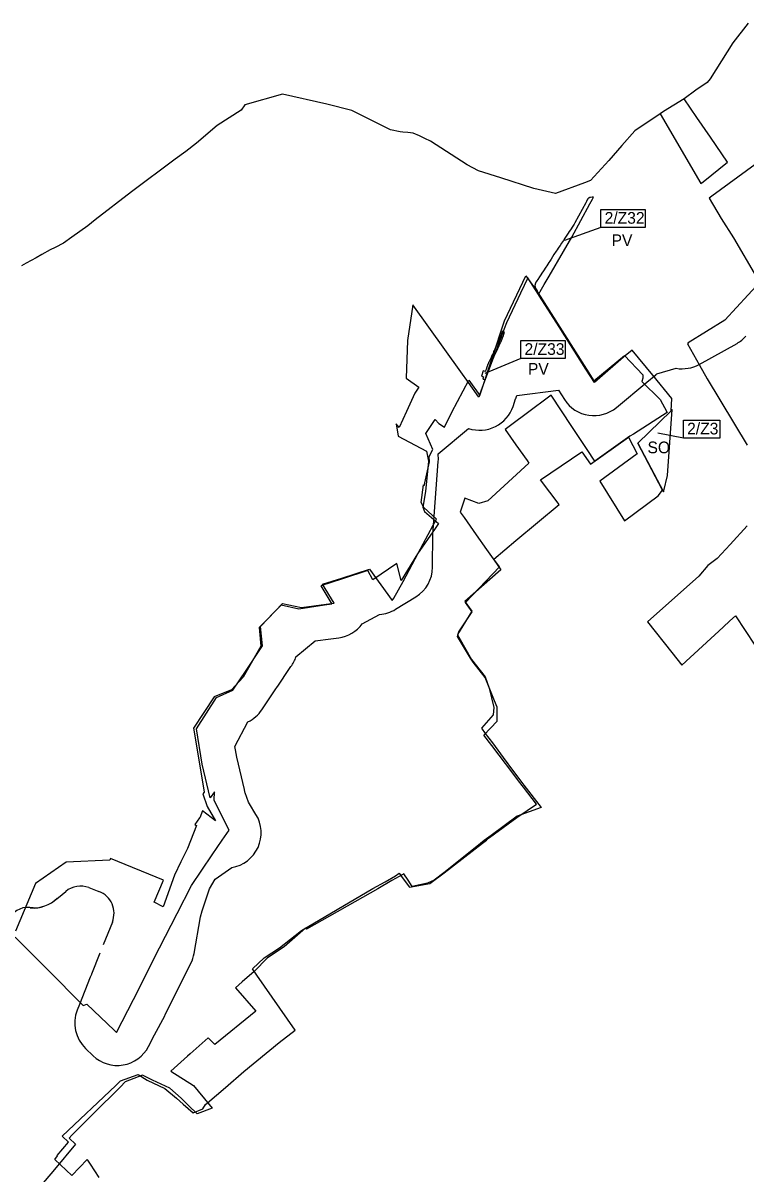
# Model space of a CAD drawing. Extents: x -445049 to -440454, y -1148980 to -1129741.
# Drawn here: x -442589 to -441970, y -1130999 to -1130014 of the extents above; entities that cross this region are included whole.
import ezdxf

# ---------------------------------------------------------------- set-up
doc = ezdxf.new("R2010")
doc.units = 0
for name, color, linetype in [('Vrstva 12', 7, 'Continuous'), ('Vrstva 23', 7, 'Continuous'), ('Vrstva 3', 7, 'Continuous'), ('Vrstva 4', 7, 'Continuous'), ('Vrstva 5', 7, 'Continuous'), ('Vrstva 7', 7, 'Continuous'), ('Vrstva 8', 7, 'Continuous')]:
    doc.layers.add(name, color=color, linetype=linetype)

msp = doc.modelspace()

# ---------------------------------------------------------------- linework, layer by layer
at = {"layer": 'Vrstva 12'}
for points in [[(-442595.33, -1130796.33), (-442567.97, -1130823.69), (-442537.17, -1130854.81), (-442534.01, -1130853.68), (-442510.71, -1130876.08), (-442508.8, -1130877.87), (-442494, -1130849.69), (-442471.86, -1130805.4), (-442456.75, -1130776.14), (-442444.4, -1130752.19), (-442426.73, -1130725.96), (-442418.12, -1130713.48), (-442412.16, -1130704.79), (-442417.54, -1130694.16), (-442425.19, -1130679.05), (-442424.78, -1130672.08), (-442428.44, -1130677.27), (-442435.36, -1130648.36), (-442440.31, -1130618.11), (-442423.19, -1130591.29), (-442409.17, -1130585.11), (-442397.74, -1130568.15), (-442385.38, -1130549.49), (-442383.66, -1130547.16), (-442385.44, -1130530.65), (-442366.47, -1130510.85), (-442350.38, -1130514.29), (-442329.37, -1130511.49), (-442322.54, -1130510.58), (-442332.33, -1130494.4), (-442315.71, -1130489.1), (-442292.1, -1130481.42), (-442272.76, -1130508.34), (-442271.22, -1130506.26), (-442263.49, -1130491.97), (-442250.42, -1130467.82), (-442237.6, -1130443.82), (-442234.92, -1130438.8), (-442245.62, -1130428.63), (-442248.08, -1130424.54), (-442245.98, -1130409.38), (-442245.35, -1130410.02), (-442240.91, -1130389.61), (-442241.22, -1130385.01), (-442237.84, -1130379.07), (-442243.89, -1130365.44), (-442237.68, -1130355.97), (-442235.9, -1130353.26), (-442232.72, -1130356.94), (-442228.11, -1130359.84), (-442221.58, -1130347.01), (-442207.18, -1130319.76), (-442197.84, -1130332.75), (-442176.55, -1130268.98), (-442158.26, -1130230.57), (-442148.19, -1130244.82), (-442106.57, -1130310.46), (-442100.18, -1130320.2), (-442074.1, -1130298.53), (-442058.25, -1130315.27), (-442058.25, -1130317.93), (-442059.21, -1130321), (-442043.4, -1130336.28), (-442037.79, -1130346.95), (-442037.5, -1130347.51), (-442066.33, -1130365.86), (-442069.31, -1130367.76), (-442099.33, -1130389.02), (-442105.89, -1130379.11), (-442119.05, -1130359.26), (-442136.78, -1130332.49), (-442143.58, -1130337.59), (-442151.29, -1130343.38), (-442176.07, -1130362), (-442166.84, -1130375.02), (-442157.39, -1130388.36)], [(-442157.39, -1130388.36), (-442155.79, -1130390.62), (-442190.84, -1130423.07), (-442198.75, -1130425.18), (-442210.49, -1130420.8), (-442214.52, -1130432.78), (-442211.26, -1130437.33), (-442200.9, -1130452.03), (-442192.09, -1130464.49), (-442183.61, -1130476.48), (-442179.75, -1130481.95), (-442210.58, -1130509.12), (-442204.65, -1130517.48), (-442214.6, -1130533.69), (-442216.83, -1130537.32), (-442215.59, -1130539.55), (-442205, -1130558.64), (-442193.23, -1130573.46), (-442189.88, -1130583.3), (-442185.72, -1130599.94), (-442186.23, -1130606.23), (-442196.21, -1130617.38), (-442193.26, -1130622.07), (-442186.81, -1130630.2), (-442177.66, -1130642.74), (-442169.04, -1130654.56), (-442164.52, -1130660.57), (-442160.11, -1130666.3), (-442145.37, -1130685.45), (-442165.7, -1130692.86), (-442188, -1130709.36), (-442193.96, -1130713.78), (-442197.24, -1130716.21), (-442211.33, -1130727.52), (-442227.28, -1130740.32), (-442236.75, -1130747.52), (-442242.49, -1130750.29), (-442255.53, -1130752.86), (-442259.11, -1130747.53), (-442262.67, -1130742.04), (-442266.77, -1130744.41), (-442272.95, -1130747.99), (-442285.14, -1130754.91), (-442346.19, -1130789.58), (-442347.06, -1130788.54), (-442365.29, -1130804.56), (-442379.44, -1130814.11), (-442390.73, -1130825.7), (-442401.06, -1130834.54), (-442406.79, -1130839.78), (-442389.51, -1130859.77), (-442424.57, -1130888.24), (-442430.16, -1130882.46), (-442445.76, -1130896.28), (-442447.99, -1130898.25), (-442462.24, -1130910.88), (-442442.91, -1130923.26), (-442429.29, -1130939.58), (-442426.78, -1130942.6), (-442439.62, -1130947.54), (-442446.91, -1130940.41), (-442453.29, -1130934.16), (-442463.09, -1130925.6), (-442477.96, -1130918.61), (-442486.35, -1130914.53), (-442501.14, -1130920.13), (-442505.34, -1130924.33), (-442528.53, -1130947.56), (-442546.81, -1130965.9), (-442549.28, -1130968.38), (-442543.73, -1130973.46), (-442561.81, -1130995.09), (-442574.69, -1131010.37)]]:
    msp.add_lwpolyline(points, dxfattribs=at)
at = {"layer": 'Vrstva 23'}
for p, q in [((-442010.07, -1130306.23), (-441977.69, -1130288.24)), ((-442046.9, -1130314.86), (-442046.85, -1130314.82)), ((-442046.55, -1130314.56), (-442046.23, -1130314.28)), ((-442046.23, -1130314.28), (-442029.67, -1130309.58)), ((-442169.3, -1130342.16), (-442167.1, -1130335.6)), ((-442166.23, -1130332.98), (-442130.47, -1130328.43)), ((-442080.84, -1130343.07), (-442080.77, -1130343.01)), ((-442233.5, -1130382.83), (-442207.32, -1130361.03)), ((-442237.56, -1130447.91), (-442233.27, -1130389.3)), ((-442269.79, -1130515.78), (-442252.39, -1130505.03)), ((-442298.31, -1130528.25), (-442283.56, -1130520.19)), ((-442355.07, -1130556.41), (-442338.73, -1130542.86)), ((-442372.76, -1130584.76), (-442370.84, -1130581.91)), ((-442384.19, -1130601.72), (-442372.76, -1130584.76)), ((-442407.29, -1130633.32), (-442396.16, -1130612.04)), ((-442406.85, -1130636.05), (-442407.29, -1130633.32)), ((-442395.79, -1130680.81), (-442398.63, -1130672.99)), ((-442394.89, -1130682.25), (-442395.79, -1130680.81)), ((-442389.31, -1130691.28), (-442394.85, -1130682.32)), ((-442424.34, -1130746.69), (-442410.05, -1130736.68)), ((-442532.26, -1130753.97), (-442523.64, -1130757.25)), ((-442512.21, -1130783.45), (-442520.09, -1130802.92)), ((-442522.84, -1130809.98), (-442530.11, -1130828.11)), ((-442467.07, -1130862.95), (-442444.93, -1130818.67)), ((-442535.14, -1130891.55), (-442528.66, -1130897.77))]:
    msp.add_line(p, q, dxfattribs=at)
for points in [[(-442080.77, -1130343.01), (-442054.82, -1130321.45), (-442047.26, -1130315.16)], [(-442167.08, -1130335.54), (-442166.23, -1130332.98)], [(-442130.47, -1130328.43), (-442125.3, -1130336.41)], [(-442238.16, -1130479.84), (-442237.85, -1130451.84), (-442237.6, -1130448.37), (-442237.57, -1130448.02)], [(-442338.73, -1130542.86), (-442325.31, -1130541.07), (-442318.48, -1130540.16)], [(-442370.7, -1130581.69), (-442360.66, -1130566.51), (-442359.39, -1130564.78)], [(-442399.16, -1130670.13), (-442405.83, -1130642.28), (-442406.85, -1130636.06)], [(-442442.18, -1130810.24), (-442436.91, -1130778.98), (-442435.33, -1130773.92), (-442429, -1130755.07), (-442424.34, -1130746.69)], [(-442564.26, -1130766.9), (-442558.37, -1130762.4), (-442552.06, -1130757.21)], [(-442580.01, -1130771.2), (-442579.46, -1130771.31), (-442574.9, -1130771.09), (-442570.05, -1130769.53)], [(-442530.17, -1130828.26), (-442531.12, -1130830.67), (-442540.32, -1130853.95), (-442542.27, -1130858.89)], [(-442481.26, -1130889.97), (-442476.07, -1130880), (-442467.38, -1130863.56)]]:
    msp.add_lwpolyline(points, dxfattribs=at)
for centre, radius, start, end in [((-441992.26, -1130262.02), 30, 299.04961, 317.88381), ((-442024.64, -1130280), 30, 260.34916, 299.04961), ((-442066.43, -1130292.09), 30, 309.71822, 310.60129), ((-442066.37, -1130292.04), 30, 310.60129, 311.35266), ((-442195.54, -1130326.04), 30, 341.42692, 341.55156), ((-442100.13, -1130320.09), 30, 212.95313, 310.00319), ((-442197.74, -1130332.6), 30, 251.38675, 341.42692), ((-442263.19, -1130387.11), 30, 355.81115, 8.18805), ((-442267.48, -1130445.72), 30, 355.60129, 355.81115), ((-442268.16, -1130479.51), 30, 301.70362, 359.36568), ((-442285.55, -1130490.25), 30, 273.81135, 301.70362), ((-442322.44, -1130510.42), 30, 277.58821, 323.53363), ((-442383.56, -1130547), 30, 323.65489, 341.71934), ((-442395.73, -1130565.15), 30, 326.03873, 326.54572), ((-442397.64, -1130568), 30, 326.03056, 326.03873), ((-442409.07, -1130584.95), 30, 295.47934, 326.03056), ((-442436.45, -1130640.9), 30, 9.29087, 9.30091), ((-442428.34, -1130677.12), 30, 7.90731, 13.45737), ((-442414.82, -1130707.06), 30, 279.15439, 31.75088), ((-442420.36, -1130698.11), 30, 31.75088, 31.8988), ((-442539.36, -1130772.67), 20, 69.19358, 129.39509), ((-442530.75, -1130775.94), 20, 337.95559, 69.19358), ((-442580.17, -1130741.29), 30.13, 265.67538, 313.84022), ((-442583.92, -1130790.81), 20, 78.7334, 211.51649), ((-442471.76, -1130805.25), 30, 333.43596, 350.4264), ((-442502.27, -1130839.27), 30, 158.15511, 158.47063), ((-442514.36, -1130869.91), 30, 158.44922, 226.16196), ((-442493.9, -1130849.53), 30, 332.13166, 333.43596), ((-442507.88, -1130876.13), 30, 226.16196, 332.53082)]:
    msp.add_arc(centre, radius, start, end, dxfattribs=at)
at = {"layer": 'Vrstva 3'}
for p, q in [((-442094.13, -1130189.04), (-442125.34, -1130200.08)), ((-442094.13, -1130189.04), (-442125.34, -1130200.08)), ((-442162.66, -1130301.29), (-442193.37, -1130313.99)), ((-442023.56, -1130369.34), (-442045.31, -1130365.08))]:
    msp.add_line(p, q, dxfattribs=at)
for points in [[(-442094.13, -1130173.64), (-442056.27, -1130173.64), (-442056.27, -1130189.04), (-442094.13, -1130189.04)], [(-442162.66, -1130285.89), (-442124.8, -1130285.89), (-442124.8, -1130301.29), (-442162.66, -1130301.29)], [(-442023.56, -1130353.94), (-441992.34, -1130353.94), (-441992.34, -1130369.34), (-442023.56, -1130369.34)]]:
    msp.add_lwpolyline(points, close=True, dxfattribs=at)
at = {"layer": 'Vrstva 5'}
msp.add_lwpolyline([(-441968.28, -1130014.12), (-441981.34, -1130031.18), (-442000.52, -1130061.9), (-442003.19, -1130064.95), (-442012.81, -1130071.6), (-442023.03, -1130078.94), (-442040.49, -1130089.83), (-442043.55, -1130091.73), (-442065.09, -1130106.34), (-442076.18, -1130118.93), (-442087.43, -1130131.7), (-442103.14, -1130148.98), (-442108.13, -1130150.84), (-442133.05, -1130160.12), (-442151.52, -1130155.69), (-442179.75, -1130146.73), (-442198.81, -1130140.68), (-442208.69, -1130135.57), (-442239.96, -1130115.3), (-442244.72, -1130113.01), (-442249.43, -1130110.78), (-442254.8, -1130108.24), (-442259.29, -1130107.93), (-442263.59, -1130107.63), (-442265.82, -1130107.18), (-442274.14, -1130105.52), (-442307.27, -1130088.94), (-442328.7, -1130083.45), (-442366.7, -1130075), (-442398.74, -1130084.23), (-442401.87, -1130088.8), (-442422.55, -1130101.82), (-442440.11, -1130116.81), (-442449.29, -1130123.99), (-442458.56, -1130130.67), (-442495.88, -1130158.65), (-442526.91, -1130182.42), (-442533.24, -1130187.55), (-442546.96, -1130197.32), (-442553.93, -1130202.46), (-442561.26, -1130206.13), (-442565.36, -1130208.18), (-442572.43, -1130212.23), (-442577.49, -1130215), (-442586.03, -1130219.67), (-442590.09, -1130221.92)], dxfattribs=at)
at = {"layer": 'Vrstva 7'}
for points in [[(-442023.03, -1130078.94), (-442040.49, -1130089.83), (-442043.55, -1130091.73), (-442008.73, -1130151.56), (-442006.58, -1130149.9), (-441985.76, -1130133.14), (-442000.4, -1130111.93), (-442012.05, -1130094.94)], [(-441930.01, -1130111.7), (-441954.77, -1130129.82), (-441999.12, -1130162.3), (-442001.53, -1130163.93), (-441991.33, -1130181.45), (-441980.69, -1130198.01), (-441960.97, -1130231.52), (-441960.55, -1130231), (-441958.88, -1130228.78), (-441957.66, -1130227.15), (-441943.76, -1130207.1), (-441912.46, -1130162.04), (-441911.1, -1130160.09), (-441904.93, -1130149.58), (-441903.73, -1130144.95), (-441920.05, -1130125.43)]]:
    msp.add_lwpolyline(points, close=True, dxfattribs=at)
for points in [[(-442523.39, -1131002), (-442530.97, -1130990.64), (-442533.27, -1130987.19), (-442533.76, -1130986.69), (-442546.93, -1131000.27), (-442561.55, -1130986.49), (-442559.09, -1130983.59), (-442559.43, -1130983.26), (-442549.66, -1130971.66), (-442555.24, -1130966.51), (-442509.17, -1130923.26), (-442505.12, -1130919.19), (-442489.99, -1130913.82), (-442482.31, -1130918.64), (-442467.23, -1130925.9), (-442457.39, -1130934.18), (-442451.67, -1130939.17), (-442443.02, -1130946.72), (-442434.77, -1130943.19), (-442432.43, -1130939.66), (-442430.71, -1130938.16), (-442415.46, -1130924.89), (-442399.82, -1130911.29), (-442369.58, -1130886.47), (-442355.66, -1130875.84), (-442388.67, -1130828.76), (-442392.3, -1130823.57), (-442382.16, -1130814.06), (-442369.16, -1130805.42), (-442355.76, -1130794.99), (-442350.26, -1130790.71), (-442289.19, -1130754.75), (-442278.85, -1130749), (-442270.03, -1130743.79), (-442266.87, -1130741.62), (-442263.34, -1130746.47), (-442257.88, -1130753.57), (-442240.43, -1130750.31), (-442228.19, -1130741.37), (-442195.33, -1130715.79), (-442192.06, -1130713.25), (-442189.35, -1130711.14), (-442166.1, -1130694.05), (-442149.21, -1130682.6), (-442160.45, -1130667.9), (-442164.59, -1130662.49), (-442169.6, -1130655.94), (-442187.59, -1130632.41), (-442194.29, -1130623.51), (-442182.95, -1130611.59), (-442183.02, -1130599.45), (-442185.2, -1130594.11), (-442193.3, -1130574.26), (-442203.58, -1130560.96), (-442205.64, -1130557.55), (-442216.78, -1130539.09), (-442215.64, -1130535.21), (-442204.32, -1130518.01), (-442210.02, -1130510.1), (-442180.85, -1130479.54), (-442185.69, -1130472.83), (-442166.82, -1130457.05), (-442129.74, -1130426.05), (-442145.71, -1130404.93), (-442110.41, -1130380.99), (-442103.13, -1130391.6), (-442070.44, -1130368.51), (-442063.15, -1130382.88), (-442095.19, -1130406.3), (-442074.02, -1130440), (-442045.02, -1130418.63), (-442041.44, -1130413.72), (-442062.64, -1130373.74), (-442034.16, -1130345.84), (-442033.47, -1130335.34), (-442049.81, -1130315.35), (-442067.32, -1130293.93), (-442074.76, -1130300.09), (-442099.77, -1130321.66), (-442106.94, -1130310.35), (-442129.93, -1130274.13), (-442146.68, -1130247.73), (-442147.42, -1130246.56), (-442156.61, -1130232.08), (-442162.91, -1130245.24), (-442175.02, -1130270.55), (-442177.01, -1130275.79), (-442196.71, -1130328.15), (-442198.59, -1130334.16), (-442207.43, -1130321.84), (-442214.01, -1130312.67), (-442255.19, -1130255.32), (-442259.71, -1130285.84), (-442260.9, -1130318.15), (-442250.08, -1130325.62), (-442253.24, -1130330.91), (-442260.54, -1130346.62), (-442266.83, -1130360.15), (-442269.48, -1130357.09), (-442267.55, -1130367.73), (-442243.5, -1130380.36), (-442241.73, -1130389.05), (-442244.31, -1130414.87), (-442246.63, -1130428.44), (-442245.12, -1130432.2), (-442233.24, -1130442.46), (-442236.05, -1130446.74), (-442251.02, -1130468.25), (-442264.98, -1130491.16), (-442268.82, -1130476.66), (-442289.19, -1130490.62), (-442293.61, -1130482.67), (-442316.03, -1130489.94), (-442333.77, -1130495.69), (-442324.36, -1130511.4), (-442330.75, -1130512.4), (-442352.69, -1130515.83), (-442367.7, -1130512.32), (-442386.53, -1130531.38), (-442385.24, -1130547.32), (-442400.28, -1130573.85), (-442410.35, -1130584.67), (-442425.08, -1130590.72), (-442442.7, -1130617.43), (-442438.82, -1130641.1), (-442433.7, -1130672.39), (-442434.7, -1130673.66), (-442431.18, -1130684.47), (-442423.92, -1130696.8), (-442435.09, -1130688.21), (-442437.48, -1130694.27), (-442437.57, -1130694.2), (-442441.55, -1130699.9), (-442440.11, -1130700.91), (-442447.89, -1130720.58), (-442453.47, -1130731.84), (-442459.12, -1130743.22), (-442468.64, -1130770.49), (-442476.35, -1130766.33), (-442468.55, -1130747.56), (-442513.88, -1130729.11), (-442514.5, -1130730.61), (-442551.85, -1130732.3), (-442577.91, -1130750.47), (-442595.19, -1130791.2)], [(-441958.19, -1130235.92), (-441988.2, -1130268.26), (-442019.41, -1130287.89), (-442020.01, -1130288.63), (-442009.86, -1130306.84), (-442003.11, -1130318.57), (-441968.88, -1130375.49)], [(-441968.88, -1130444.52), (-441983.46, -1130460.27), (-441994.71, -1130472.41), (-442002.76, -1130478.43), (-442010.45, -1130487.45), (-442054.28, -1130526.46), (-442033.46, -1130552.66), (-442024.8, -1130563.56), (-441989.51, -1130531.02), (-441983.81, -1130525.77), (-441979.02, -1130521.35), (-441962.3, -1130546.62)]]:
    msp.add_lwpolyline(points, dxfattribs=at)
at = {"layer": 'Vrstva 8'}
for points in [[(-442100.41, -1130163.19), (-442100.5, -1130163.19), (-442101.62, -1130163.23), (-442102.97, -1130163.32), (-442103.06, -1130163.33), (-442103.19, -1130163.34), (-442103.23, -1130163.35), (-442103.26, -1130163.35), (-442103.31, -1130163.36), (-442103.36, -1130163.37), (-442103.49, -1130163.39), (-442103.61, -1130163.42), (-442103.67, -1130163.44), (-442103.71, -1130163.45), (-442103.77, -1130163.47), (-442103.83, -1130163.49), (-442103.87, -1130163.51), (-442103.92, -1130163.53), (-442103.97, -1130163.55), (-442104.04, -1130163.58), (-442104.1, -1130163.61), (-442104.19, -1130163.65), (-442104.25, -1130163.68), (-442104.3, -1130163.71), (-442104.35, -1130163.74), (-442104.45, -1130163.8), (-442104.53, -1130163.85), (-442104.59, -1130163.89), (-442104.71, -1130163.99), (-442104.78, -1130164.04), (-442104.85, -1130164.11), (-442104.9, -1130164.15), (-442104.97, -1130164.22), (-442105.02, -1130164.27), (-442105.09, -1130164.35), (-442105.14, -1130164.4), (-442105.2, -1130164.48), (-442105.25, -1130164.54), (-442105.3, -1130164.61), (-442105.34, -1130164.67), (-442105.38, -1130164.74), (-442105.42, -1130164.81), (-442105.44, -1130164.84), (-442105.45, -1130164.86), (-442105.48, -1130164.92), (-442106.45, -1130166.9), (-442107.03, -1130168.06), (-442116.47, -1130185.1), (-442117.12, -1130186.16), (-442118.22, -1130187.93), (-442118.84, -1130188.91), (-442119.72, -1130190.29), (-442120.23, -1130191.08), (-442121.24, -1130192.62), (-442122.2, -1130194.07), (-442123.92, -1130196.6), (-442125.14, -1130198.35), (-442126.28, -1130200.08), (-442127.8, -1130202.41), (-442129.08, -1130204.36), (-442130.02, -1130205.81), (-442130.61, -1130206.7), (-442131.6, -1130208.22), (-442132.34, -1130209.36), (-442134.29, -1130212.34), (-442135.51, -1130214.21), (-442136.79, -1130216.18), (-442137.85, -1130217.8), (-442138.74, -1130219.16), (-442139.61, -1130220.49), (-442140.46, -1130221.79), (-442141.36, -1130223.16), (-442143.34, -1130226.2), (-442144.62, -1130228.16), (-442145.66, -1130229.74), (-442146.65, -1130231.27), (-442148.22, -1130233.66), (-442148.92, -1130234.73), (-442149.45, -1130235.55), (-442149.72, -1130235.96), (-442149.81, -1130236.1), (-442149.92, -1130236.29), (-442149.99, -1130236.41), (-442150.07, -1130236.56), (-442150.18, -1130236.8), (-442150.26, -1130237.01), (-442150.34, -1130237.24), (-442150.4, -1130237.43), (-442150.42, -1130237.53), (-442150.46, -1130237.67), (-442150.49, -1130237.85), (-442150.53, -1130238.03), (-442150.54, -1130238.18), (-442150.56, -1130238.33), (-442150.58, -1130238.59), (-442150.58, -1130238.76), (-442150.58, -1130238.87), (-442150.57, -1130239.07), (-442150.56, -1130239.21), (-442150.55, -1130239.34), (-442150.51, -1130239.62), (-442150.46, -1130239.84), (-442150.42, -1130240.01), (-442150.38, -1130240.15), (-442150.33, -1130240.32), (-442150.27, -1130240.49), (-442150.22, -1130240.63), (-442150.18, -1130240.72), (-442150.13, -1130240.84), (-442150.06, -1130240.99), (-442149.98, -1130241.13), (-442149.8, -1130241.46), (-442149.25, -1130242.49), (-442148.79, -1130243.34), (-442148.44, -1130243.99), (-442147.42, -1130246.56), (-442144.97, -1130241.74), (-442142.74, -1130237.95), (-442140.97, -1130234.93), (-442138.56, -1130230.82), (-442126.12, -1130209.62), (-442119.05, -1130197.42), (-442103.51, -1130168.88), (-442101.29, -1130164.8)], [(-442176.56, -1130278.6), (-442178.52, -1130277.9), (-442179.04, -1130279.33), (-442179.38, -1130280.27), (-442179.78, -1130281.39), (-442180.11, -1130282.3), (-442180.48, -1130283.31), (-442180.67, -1130283.8), (-442180.85, -1130284.28), (-442181.01, -1130284.64), (-442181.25, -1130285.2), (-442181.45, -1130285.65), (-442181.6, -1130285.99), (-442181.83, -1130286.48), (-442182.01, -1130286.88), (-442182.33, -1130287.58), (-442182.53, -1130288.02), (-442182.67, -1130288.32), (-442182.9, -1130288.81), (-442183.11, -1130289.27), (-442183.5, -1130290.12), (-442184.07, -1130291.35), (-442184.32, -1130291.9), (-442184.56, -1130292.43), (-442184.96, -1130293.31), (-442185.22, -1130293.87), (-442185.4, -1130294.25), (-442185.63, -1130294.75), (-442186.02, -1130295.6), (-442186.47, -1130296.59), (-442186.98, -1130297.69), (-442187.44, -1130298.69), (-442188.17, -1130300.29), (-442188.76, -1130301.57), (-442189.2, -1130302.52), (-442189.48, -1130303.15), (-442189.87, -1130303.99), (-442190.07, -1130304.43), (-442190.2, -1130304.7), (-442190.39, -1130305.11), (-442190.52, -1130305.41), (-442190.64, -1130305.68), (-442190.75, -1130305.92), (-442190.91, -1130306.3), (-442190.98, -1130306.46), (-442191.07, -1130306.69), (-442191.19, -1130306.97), (-442191.29, -1130307.24), (-442191.46, -1130307.66), (-442191.61, -1130308.06), (-442191.71, -1130308.34), (-442191.8, -1130308.59), (-442191.9, -1130308.88), (-442192.01, -1130309.19), (-442192.16, -1130309.65), (-442192.45, -1130310.51), (-442192.68, -1130311.2), (-442192.82, -1130311.63), (-442193.03, -1130312.27), (-442194.76, -1130311.69), (-442196.3, -1130316.37), (-442194.57, -1130316.95), (-442195.2, -1130318.83), (-442193.26, -1130319.47), (-442193.11, -1130319.51), (-442193.05, -1130319.19), (-442192.99, -1130318.92), (-442192.94, -1130318.69), (-442192.84, -1130318.36), (-442192.79, -1130318.17), (-442192.73, -1130317.99), (-442192.61, -1130317.62), (-442192.5, -1130317.29), (-442192.36, -1130316.86), (-442192.15, -1130316.25), (-442192, -1130315.77), (-442191.68, -1130314.82), (-442191.31, -1130313.7), (-442191, -1130312.76), (-442190.6, -1130311.55), (-442190.32, -1130310.71), (-442189.9, -1130309.46), (-442189.68, -1130308.83), (-442189.47, -1130308.28), (-442189.37, -1130308.02), (-442189.31, -1130307.89), (-442189.27, -1130307.77), (-442189.16, -1130307.52), (-442189.05, -1130307.23), (-442188.96, -1130307.04), (-442188.9, -1130306.89), (-442188.8, -1130306.64), (-442188.7, -1130306.43), (-442188.55, -1130306.09), (-442188.45, -1130305.89), (-442188.38, -1130305.73), (-442188.3, -1130305.55), (-442188.21, -1130305.35), (-442188.11, -1130305.15), (-442187.86, -1130304.6), (-442187.68, -1130304.21), (-442187.45, -1130303.7), (-442187.32, -1130303.41), (-442187.14, -1130303.03), (-442186.95, -1130302.6), (-442186.73, -1130302.14), (-442186.51, -1130301.65), (-442186.27, -1130301.13), (-442185.96, -1130300.45), (-442185.6, -1130299.66), (-442185.39, -1130299.22), (-442185.16, -1130298.71), (-442184.78, -1130297.9), (-442184.54, -1130297.36), (-442184.08, -1130296.37), (-442183.77, -1130295.69), (-442183.44, -1130294.98), (-442183.01, -1130294.05), (-442182.7, -1130293.37), (-442182.31, -1130292.52), (-442182.05, -1130291.94), (-442181.57, -1130290.9), (-442181.19, -1130290.08), (-442180.94, -1130289.54), (-442180.65, -1130288.91), (-442180.38, -1130288.32), (-442180.05, -1130287.6), (-442179.86, -1130287.19), (-442179.6, -1130286.62), (-442179.45, -1130286.27), (-442179.3, -1130285.94), (-442179.17, -1130285.63), (-442179.01, -1130285.26), (-442178.84, -1130284.84), (-442178.74, -1130284.59), (-442178.55, -1130284.11), (-442178.47, -1130283.88), (-442178.36, -1130283.58), (-442178.26, -1130283.3), (-442178.16, -1130283.03), (-442177.61, -1130281.49), (-442177.5, -1130281.2), (-442177.29, -1130280.63), (-442177.16, -1130280.26)], [(-442033.22, -1130344.78), (-442034.16, -1130345.84), (-442062.64, -1130373.74), (-442040.67, -1130415.17), (-442040.16, -1130414.3), (-442037.16, -1130401.29)]]:
    msp.add_lwpolyline(points, close=True, dxfattribs=at)

# ---------------------------------------------------------------- texts
at = {"layer": 'Vrstva 3'}
for s, p in [('2/Z32', (-442090.96, -1130185.86)), ('2/Z33', (-442159.49, -1130298.11)), ('2/Z3', (-442020.39, -1130366.16))]:
    msp.add_text(s, height=10, dxfattribs=at).set_placement(p)
at = {"layer": 'Vrstva 4'}
for s, p in [('PV', (-442085.03, -1130205.03)), ('PV', (-442156.62, -1130315.08)), ('SO', (-442054.29, -1130382.26)), ('SO', (-442054.29, -1130382.26))]:
    msp.add_text(s, height=10, dxfattribs=at).set_placement(p)

doc.saveas('drawing.dxf')
